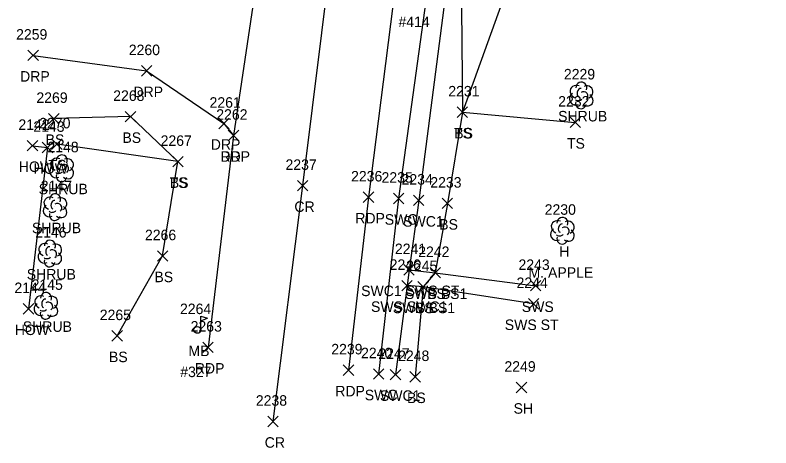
# Model space of a CAD drawing. Extents: x 1651305 to 1654558, y 539481 to 548441.
# Drawn here: x 1654299.3 to 1654443.3, y 544058 to 544140.4 of the extents above; entities that cross this region are included whole.
import ezdxf

# ---------------------------------------------------------------- set-up
doc = ezdxf.new("R2010")
doc.units = 0
for name, color, linetype in [('L_A', 7, 'Continuous'), ('L_C', 7, 'Continuous'), ('L_I', 7, 'Continuous'), ('L_TIC', 7, 'Continuous'), ('LBC', 7, 'Continuous'), ('LELB', 7, 'Continuous'), ('LMB', 7, 'Continuous'), ('LSH', 7, 'Continuous'), ('LTD', 7, 'Continuous'), ('P_A', 7, 'Continuous'), ('P_I', 7, 'Continuous'), ('P_TIC', 7, 'Continuous'), ('PET', 7, 'Continuous'), ('PRC', 7, 'Continuous'), ('R_A', 7, 'Continuous'), ('R_I', 7, 'Continuous'), ('R_TIC', 7, 'Continuous'), ('RDP', 7, 'Continuous'), ('RSW', 7, 'Continuous'), ('U_C', 7, 'Continuous')]:
    doc.layers.add(name, color=color, linetype=linetype)

msp = doc.modelspace()

# ---------------------------------------------------------------- linework, layer by layer
at = {"layer": 'L_TIC'}
for points in [[(1654383.51, 544120.92), (1654385.51, 544122.92)], [(1654385.51, 544120.92), (1654383.51, 544122.92)], [(1654383.51, 544120.92), (1654385.51, 544122.92)], [(1654385.51, 544120.92), (1654383.51, 544122.92)], [(1654305.68, 544119.69), (1654307.68, 544121.69)], [(1654307.68, 544119.69), (1654305.68, 544121.69)], [(1654320.3, 544120.07), (1654322.3, 544122.07)], [(1654322.3, 544120.07), (1654320.3, 544122.07)], [(1654405.01, 544118.98), (1654407.01, 544120.98)], [(1654407.01, 544118.98), (1654405.01, 544120.98)], [(1654301.62, 544114.54), (1654303.62, 544116.54)], [(1654303.62, 544114.54), (1654301.62, 544116.54)], [(1654304.46, 544114.18), (1654306.46, 544116.18)], [(1654306.46, 544114.18), (1654304.46, 544116.18)], [(1654306.25, 544114.84), (1654308.25, 544116.84)], [(1654308.25, 544114.84), (1654306.25, 544116.84)], [(1654329.32, 544111.5), (1654331.32, 544113.5)], [(1654331.32, 544111.5), (1654329.32, 544113.5)], [(1654329.32, 544111.5), (1654331.32, 544113.5)], [(1654331.32, 544111.5), (1654329.32, 544113.5)], [(1654380.65, 544103.55), (1654382.65, 544105.55)], [(1654382.65, 544103.55), (1654380.65, 544105.55)], [(1654326.4, 544093.54), (1654328.4, 544095.54)], [(1654328.4, 544093.54), (1654326.4, 544095.54)], [(1654378.35, 544090.34), (1654380.35, 544092.34)], [(1654380.35, 544090.34), (1654378.35, 544092.34)], [(1654376.04, 544087.64), (1654378.04, 544089.64)], [(1654378.04, 544087.64), (1654376.04, 544089.64)], [(1654300.86, 544083.47), (1654302.86, 544085.47)], [(1654302.86, 544083.47), (1654300.86, 544085.47)], [(1654317.74, 544078.31), (1654319.74, 544080.31)], [(1654319.74, 544078.31), (1654317.74, 544080.31)], [(1654374.52, 544070.52), (1654376.52, 544072.52)], [(1654376.52, 544070.52), (1654374.52, 544072.52)], [(1654394.77, 544068.49), (1654396.77, 544070.49)], [(1654396.77, 544068.49), (1654394.77, 544070.49)]]:
    msp.add_lwpolyline(points, dxfattribs=at)
at = {"layer": 'LBC'}
msp.add_lwpolyline([(1654302.62, 544115.54), (1654305.46, 544115.18), (1654301.86, 544084.47)], dxfattribs=at)
at = {"layer": 'LELB'}
for points in [[(1654389.75, 544182.63), (1654384.25, 544148.47), (1654384.51, 544121.92), (1654406.01, 544119.98)], [(1654417.94, 544173.72), (1654397.83, 544177.38), (1654393.47, 544146.84), (1654384.51, 544121.92), (1654381.65, 544104.55), (1654379.35, 544091.34), (1654377.04, 544088.64), (1654375.52, 544071.52)], [(1654318.74, 544079.31), (1654327.4, 544094.54), (1654330.32, 544112.5), (1654321.3, 544121.07), (1654306.68, 544120.69)], [(1654330.32, 544112.5), (1654307.25, 544115.84)]]:
    msp.add_lwpolyline(points, dxfattribs=at)
at = {"layer": 'LMB'}
for p, q in [((1654334.67, 544083.06), (1654335.96, 544082.68)), ((1654334.67, 544080.47), (1654334.67, 544083.06)), ((1654334.67, 544082.16), (1654335.95, 544082.67)), ((1654334.02, 544080.46), (1654334.02, 544080.46))]:
    msp.add_line(p, q, dxfattribs=at)
msp.add_circle((1654334.02, 544080.46), 0.656, dxfattribs=at)
at = {"layer": 'LSH'}
for p, q in [((1654407.11, 544125.16), (1654407.11, 544125.16)), ((1654407.11, 544125.16), (1654407.11, 544125.16)), ((1654308.16, 544111.29), (1654308.16, 544111.29)), ((1654308.16, 544111.29), (1654308.16, 544111.29)), ((1654306.88, 544103.87), (1654306.88, 544103.87)), ((1654306.88, 544103.87), (1654306.88, 544103.87)), ((1654305.89, 544095.05), (1654305.89, 544095.05)), ((1654305.89, 544095.05), (1654305.89, 544095.05)), ((1654305.14, 544085.08), (1654305.14, 544085.08)), ((1654305.14, 544085.08), (1654305.14, 544085.08))]:
    msp.add_line(p, q, dxfattribs=at)
for centre in [(1654407.16, 544126.6), (1654308.2, 544112.72), (1654306.93, 544105.31), (1654305.94, 544096.48), (1654305.19, 544086.52)]:
    msp.add_arc(centre, 1.05, 335.5272, 180.9563, dxfattribs=at)
for centre, major_axis, ratio, start_param, end_param in [((1654406.32, 544125.83), (1.21, -0.51), 0.895232, 1.570796, 4.712389), ((1654408.15, 544125.75), (-1.14, -0.48), 0.949671, 1.570796, 4.712389), ((1654406.9, 544125.62), (-0.208, -0.792), 0.645439, 3.141593, 6.283185), ((1654407.61, 544125), (-0.5, 0.667), 0.989748, 3.141593, 6.283185), ((1654406.03, 544124.45), (0.58, -1.04), 0.959034, 3.141593, 6.283185), ((1654406.65, 544124.41), (-0.625, -0.083), 0.423636, 0, 3.141593), ((1654408.11, 544124.33), (-1.09, 0.79), 0.841452, 1.570796, 4.712389), ((1654407.11, 544123.66), (0.26, 1.06), 0.942809, 1.570796, 4.712389), ((1654307.36, 544111.95), (1.21, -0.51), 0.895232, 1.570796, 4.712389), ((1654309.2, 544111.87), (-1.14, -0.48), 0.949671, 1.570796, 4.712389), ((1654307.07, 544110.58), (0.58, -1.04), 0.959034, 3.141593, 6.283185), ((1654307.95, 544111.74), (-0.208, -0.792), 0.645439, 3.141593, 6.283185), ((1654308.66, 544111.12), (-0.5, 0.667), 0.989748, 3.141593, 6.283185), ((1654309.16, 544110.45), (-1.09, 0.79), 0.841452, 1.570796, 4.712389), ((1654308.16, 544109.79), (0.26, 1.06), 0.942809, 1.570796, 4.712389), ((1654307.7, 544110.54), (-0.625, -0.083), 0.423636, 0, 3.141593), ((1654306.09, 544104.54), (1.21, -0.51), 0.895232, 1.570796, 4.712389), ((1654307.92, 544104.46), (-1.14, -0.48), 0.949671, 1.570796, 4.712389), ((1654305.8, 544103.16), (0.58, -1.04), 0.959034, 3.141593, 6.283185), ((1654306.67, 544104.33), (-0.208, -0.792), 0.645439, 3.141593, 6.283185), ((1654307.38, 544103.71), (-0.5, 0.667), 0.989748, 3.141593, 6.283185), ((1654306.88, 544102.37), (0.26, 1.06), 0.942809, 1.570796, 4.712389), ((1654306.42, 544103.12), (-0.625, -0.083), 0.423636, 0, 3.141593), ((1654307.88, 544103.04), (-1.09, 0.79), 0.841452, 1.570796, 4.712389), ((1654305.1, 544095.71), (1.21, -0.51), 0.895232, 1.570796, 4.712389), ((1654306.94, 544095.63), (-1.14, -0.48), 0.949671, 1.570796, 4.712389), ((1654304.81, 544094.34), (0.58, -1.04), 0.959034, 3.141593, 6.283185), ((1654305.69, 544095.51), (-0.208, -0.792), 0.645439, 3.141593, 6.283185), ((1654306.39, 544094.88), (-0.5, 0.667), 0.989748, 3.141593, 6.283185), ((1654305.44, 544094.3), (-0.625, -0.083), 0.423636, 0, 3.141593), ((1654306.89, 544094.21), (-1.09, 0.79), 0.841452, 1.570796, 4.712389), ((1654305.89, 544093.55), (0.26, 1.06), 0.942809, 1.570796, 4.712389), ((1654304.35, 544085.75), (1.21, -0.51), 0.895232, 1.570796, 4.712389), ((1654306.18, 544085.67), (-1.14, -0.48), 0.949671, 1.570796, 4.712389), ((1654304.06, 544084.37), (0.58, -1.04), 0.959034, 3.141593, 6.283185), ((1654304.93, 544085.54), (-0.208, -0.792), 0.645439, 3.141593, 6.283185), ((1654305.64, 544084.92), (-0.5, 0.667), 0.989748, 3.141593, 6.283185), ((1654304.68, 544084.33), (-0.625, -0.083), 0.423636, 0, 3.141593), ((1654306.14, 544084.25), (-1.09, 0.79), 0.841452, 1.570796, 4.712389), ((1654305.14, 544083.58), (0.26, 1.06), 0.942809, 1.570796, 4.712389)]:
    msp.add_ellipse(centre, major_axis=major_axis, ratio=ratio, start_param=start_param, end_param=end_param, dxfattribs=at)
at = {"layer": 'LTD'}
msp.add_line((1654403.53, 544099.38), (1654403.53, 544099.38), dxfattribs=at)
msp.add_line((1654403.53, 544099.38), (1654403.53, 544099.38), dxfattribs=at)
msp.add_arc((1654403.57, 544100.82), 1.05, 335.5272, 180.9563, dxfattribs=at)
for centre, major_axis, ratio, start_param, end_param in [((1654402.73, 544100.05), (1.21, -0.51), 0.895232, 1.570796, 4.712389), ((1654404.57, 544099.97), (-1.14, -0.48), 0.949671, 1.570796, 4.712389), ((1654402.44, 544098.67), (0.58, -1.04), 0.959034, 3.141593, 6.283185), ((1654403.32, 544099.84), (-0.208, -0.792), 0.645439, 3.141593, 6.283185), ((1654404.03, 544099.22), (-0.5, 0.667), 0.989748, 3.141593, 6.283185), ((1654403.07, 544098.63), (-0.625, -0.083), 0.423636, 0, 3.141593), ((1654404.53, 544098.55), (-1.09, 0.79), 0.841452, 1.570796, 4.712389), ((1654403.53, 544097.88), (0.26, 1.06), 0.942809, 1.570796, 4.712389)]:
    msp.add_ellipse(centre, major_axis=major_axis, ratio=ratio, start_param=start_param, end_param=end_param, dxfattribs=at)
at = {"layer": 'P_TIC'}
for points in [[(1654339.92, 544116.48), (1654341.92, 544118.48)], [(1654341.92, 544116.48), (1654339.92, 544118.48)], [(1654353.07, 544106.93), (1654355.07, 544108.93)], [(1654355.07, 544106.93), (1654353.07, 544108.93)], [(1654365.61, 544104.72), (1654367.61, 544106.72)], [(1654367.61, 544104.72), (1654365.61, 544106.72)], [(1654335.05, 544076.13), (1654337.05, 544078.13)], [(1654337.05, 544076.13), (1654335.05, 544078.13)], [(1654361.8, 544071.79), (1654363.8, 544073.79)], [(1654363.8, 544071.79), (1654361.8, 544073.79)], [(1654347.42, 544062.01), (1654349.42, 544064.01)], [(1654349.42, 544062.01), (1654347.42, 544064.01)]]:
    msp.add_lwpolyline(points, dxfattribs=at)
at = {"layer": 'PET'}
for points in [[(1654345.04, 544588.36), (1654350.59, 544607.19), (1654356.58, 544624.31), (1654366.69, 544597.7), (1654378.7, 544565.63), (1654388.8, 544536.02), (1654394.39, 544506.43), (1654399.12, 544481.01), (1654401.13, 544462.89), (1654401.53, 544436.35), (1654401.83, 544421.31), (1654397.37, 544359.7), (1654394.39, 544336.59), (1654391.4, 544308.96), (1654388.94, 544290.74), (1654386.84, 544274.06), (1654380.97, 544229.45), (1654377.75, 544202.91), (1654375.63, 544181.04), (1654372.19, 544149.75), (1654366.61, 544105.72), (1654362.8, 544072.79)], [(1654345.04, 544588.36), (1654352.84, 544566.03), (1654357.71, 544551.64), (1654360.67, 544540.21), (1654367.97, 544503.91), (1654371.19, 544473.22), (1654373.31, 544432.69), (1654372.37, 544396.63), (1654369.95, 544367.4), (1654366.85, 544341.54), (1654364.49, 544322.02), (1654359.18, 544276.5), (1654356.39, 544249.38), (1654353.63, 544216.56), (1654349.27, 544178.19), (1654347.29, 544164.71), (1654345.69, 544149.48), (1654340.92, 544117.48), (1654336.05, 544077.13)]]:
    msp.add_lwpolyline(points, dxfattribs=at)
at = {"layer": 'PRC'}
msp.add_lwpolyline([(1654350.59, 544607.19), (1654355.93, 544592.7), (1654363.68, 544570.63), (1654372.22, 544542.27), (1654380.24, 544505.39), (1654384.95, 544473.92), (1654386.82, 544433.75), (1654385.71, 544395.52), (1654383.86, 544366), (1654380.92, 544339.65), (1654378, 544311.09), (1654373.89, 544274.84), (1654369.01, 544231.01), (1654366.63, 544212.46), (1654362.44, 544177.97), (1654359.49, 544151.89), (1654354.07, 544107.93), (1654348.42, 544063.01)], dxfattribs=at)
at = {"layer": 'R_TIC'}
for points in [[(1654301.76, 544131.74), (1654303.76, 544133.74)], [(1654303.76, 544131.74), (1654301.76, 544133.74)], [(1654323.35, 544128.79), (1654325.35, 544130.79)], [(1654325.35, 544128.79), (1654323.35, 544130.79)], [(1654338.08, 544118.77), (1654340.08, 544120.77)], [(1654340.08, 544118.77), (1654338.08, 544120.77)], [(1654339.92, 544116.48), (1654341.92, 544118.48)], [(1654341.92, 544116.48), (1654339.92, 544118.48)], [(1654371.36, 544104.49), (1654373.36, 544106.49)], [(1654373.36, 544104.49), (1654371.36, 544106.49)], [(1654375.18, 544104.12), (1654377.18, 544106.12)], [(1654377.18, 544104.12), (1654375.18, 544106.12)], [(1654373.34, 544090.89), (1654375.34, 544092.89)], [(1654375.34, 544090.89), (1654373.34, 544092.89)], [(1654373.34, 544090.89), (1654375.34, 544092.89)], [(1654375.34, 544090.89), (1654373.34, 544092.89)], [(1654378.35, 544090.34), (1654380.35, 544092.34)], [(1654380.35, 544090.34), (1654378.35, 544092.34)], [(1654372.97, 544087.88), (1654374.97, 544089.88)], [(1654374.97, 544087.88), (1654372.97, 544089.88)], [(1654372.97, 544087.88), (1654374.97, 544089.88)], [(1654374.97, 544087.88), (1654372.97, 544089.88)], [(1654376.04, 544087.64), (1654378.04, 544089.64)], [(1654378.04, 544087.64), (1654376.04, 544089.64)], [(1654397.45, 544087.87), (1654399.45, 544089.87)], [(1654399.45, 544087.87), (1654397.45, 544089.87)], [(1654397.08, 544084.43), (1654399.08, 544086.43)], [(1654399.08, 544084.43), (1654397.08, 544086.43)], [(1654367.55, 544071.05), (1654369.55, 544073.05)], [(1654369.55, 544071.05), (1654367.55, 544073.05)], [(1654370.75, 544070.94), (1654372.75, 544072.94)], [(1654372.75, 544070.94), (1654370.75, 544072.94)]]:
    msp.add_lwpolyline(points, dxfattribs=at)
at = {"layer": 'RDP'}
msp.add_lwpolyline([(1654302.76, 544132.74), (1654324.35, 544129.79), (1654339.08, 544119.77), (1654340.92, 544117.48)], dxfattribs=at)
at = {"layer": 'RSW'}
for points in [[(1654407.4, 544661.78), (1654407.29, 544658.87), (1654407.96, 544657.88), (1654443.27, 544654.59), (1654438.81, 544619.89), (1654433.56, 544580.17), (1654430.14, 544553.99), (1654428.03, 544537.28), (1654424.83, 544512.84), (1654419.77, 544473.61), (1654412.66, 544419.66), (1654404.12, 544354.77), (1654402.1, 544339.77), (1654395.49, 544286.06), (1654394.01, 544276.12), (1654388.39, 544229.58), (1654383.89, 544196.38), (1654382.2, 544184.33), (1654378.35, 544149.15), (1654372.36, 544105.49), (1654368.55, 544072.05)], [(1654411.79, 544225.19), (1654397.44, 544226.9), (1654391.8, 544227.25), (1654387.76, 544194.91), (1654386.47, 544185.09), (1654381.83, 544148.77), (1654376.18, 544105.12), (1654374.34, 544091.89), (1654373.97, 544088.88), (1654371.75, 544071.94)], [(1654374.34, 544091.89), (1654379.35, 544091.34), (1654398.45, 544088.87)], [(1654398.08, 544085.43), (1654377.04, 544088.64), (1654373.97, 544088.88)]]:
    msp.add_lwpolyline(points, dxfattribs=at)

# ---------------------------------------------------------------- texts
at = {"layer": 'L_A'}
for s, p in [('SHRUB', (1654402.74, 544120.16)), ('TS', (1654382.92, 544116.92)), ('BS', (1654382.95, 544116.92)), ('BS', (1654305.12, 544115.69)), ('BS', (1654319.74, 544116.07)), ('TS', (1654404.42, 544114.98)), ('TS', (1654305.66, 544110.84)), ('HOW', (1654300.01, 544110.54)), ('HOW', (1654302.84, 544110.18)), ('TS', (1654328.73, 544107.5)), ('BS', (1654328.77, 544107.5)), ('SHRUB', (1654303.79, 544106.29)), ('BS', (1654380.09, 544099.55)), ('SHRUB', (1654302.51, 544098.87)), ('H', (1654402.96, 544094.38)), ('SHRUB', (1654301.52, 544090.05)), ('BS', (1654325.84, 544089.54)), ('BS', (1654377.79, 544086.34)), ('BS', (1654375.48, 544083.64)), ('HOW', (1654299.25, 544079.47)), ('SHRUB', (1654300.77, 544080.08)), ('MB', (1654332.32, 544075.46)), ('BS', (1654317.18, 544074.31)), ('BS', (1654373.96, 544066.52)), ('SH', (1654394.26, 544064.49))]:
    msp.add_text(s, height=2, dxfattribs=at).set_placement(p)
at = {"layer": 'L_C'}
for s, p in [('M. APPLE', (1654397.1, 544090.38)), ('#327', (1654330.76, 544071.46))]:
    msp.add_text(s, height=2, dxfattribs=at).set_placement(p)
at = {"layer": 'L_I'}
for s, p in [('2229', (1654403.84, 544128.16)), ('2269', (1654303.36, 544123.69)), ('2268', (1654317.99, 544124.07)), ('2231', (1654381.82, 544124.92)), ('2231', (1654381.82, 544124.92)), ('2232', (1654402.75, 544122.98)), ('2142', (1654299.93, 544118.54)), ('2143', (1654302.77, 544118.18)), ('2270', (1654303.9, 544118.84)), ('2267', (1654327.02, 544115.5)), ('2267', (1654327.02, 544115.5)), ('2148', (1654305.46, 544114.29)), ('2147', (1654304.19, 544106.87)), ('2233', (1654378.39, 544107.55)), ('2230', (1654400.18, 544102.38)), ('2146', (1654303.15, 544098.05)), ('2266', (1654324.04, 544097.54)), ('2242', (1654376.09, 544094.34)), ('2245', (1654373.78, 544091.64)), ('2145', (1654302.45, 544088.08)), ('2144', (1654299.17, 544087.47)), ('2264', (1654330.71, 544083.46)), ('2265', (1654315.43, 544082.31)), ('2248', (1654372.26, 544074.52)), ('2249', (1654392.51, 544072.49))]:
    msp.add_text(s, height=2, dxfattribs=at).set_placement(p)
at = {"layer": 'P_A'}
for s, p in [('RDP', (1654338.41, 544112.48)), ('CR', (1654352.5, 544102.93)), ('RDP', (1654364.1, 544100.72)), ('RDP', (1654333.53, 544072.13)), ('RDP', (1654360.29, 544067.79)), ('CR', (1654346.85, 544058.01))]:
    msp.add_text(s, height=2, dxfattribs=at).set_placement(p)
at = {"layer": 'P_I'}
for s, p in [('2262', (1654337.62, 544120.48)), ('2237', (1654350.81, 544110.93)), ('2236', (1654363.3, 544108.72)), ('2263', (1654332.74, 544080.13)), ('2239', (1654359.53, 544075.79)), ('2238', (1654345.16, 544066.01))]:
    msp.add_text(s, height=2, dxfattribs=at).set_placement(p)
at = {"layer": 'R_A'}
for s, p in [('DRP', (1654300.25, 544127.74)), ('DRP', (1654321.84, 544124.79)), ('DRP', (1654336.57, 544114.77)), ('DRP', (1654338.41, 544112.48)), ('SWC', (1654369.72, 544100.49)), ('SWC1', (1654373.22, 544100.12)), ('SWC1 SWS ST', (1654365.22, 544086.89)), ('SWC1 SWS ST', (1654365.22, 544086.89)), ('SWS BS1', (1654373.55, 544086.34)), ('SWS SWC1', (1654367.1, 544083.88)), ('SWS SWC1', (1654367.1, 544083.88)), ('SWS BS1', (1654371.24, 544083.64)), ('SWS', (1654395.82, 544083.87)), ('SWS ST', (1654392.58, 544080.43)), ('SWC', (1654365.91, 544067.05)), ('SWC1', (1654368.79, 544066.94))]:
    msp.add_text(s, height=2, dxfattribs=at).set_placement(p)
at = {"layer": 'R_I'}
for s, p in [('2259', (1654299.49, 544135.74)), ('2260', (1654320.96, 544132.79)), ('2261', (1654336.34, 544122.77)), ('2262', (1654337.62, 544120.48)), ('2235', (1654369.1, 544108.49)), ('2234', (1654372.92, 544108.12)), ('2241', (1654371.65, 544094.89)), ('2241', (1654371.65, 544094.89)), ('2242', (1654376.09, 544094.34)), ('2246', (1654370.65, 544091.88)), ('2246', (1654370.65, 544091.88)), ('2245', (1654373.78, 544091.64)), ('2243', (1654395.19, 544091.87)), ('2244', (1654394.82, 544088.43)), ('2240', (1654365.2, 544075.05)), ('2247', (1654368.49, 544074.94))]:
    msp.add_text(s, height=2, dxfattribs=at).set_placement(p)
at = {"layer": 'U_C'}
msp.add_text('#414', height=2, dxfattribs=at).set_placement((1654372.33, 544138.13))

doc.saveas('drawing.dxf')
